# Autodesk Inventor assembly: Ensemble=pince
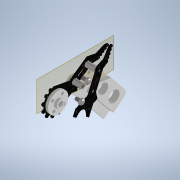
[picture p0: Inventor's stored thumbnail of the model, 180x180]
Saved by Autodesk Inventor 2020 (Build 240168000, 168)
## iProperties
Created: 2021-10
Part Number: Ensemble=pince
Document SubType Name: Assembly
Designer: bruno
Author: bruno
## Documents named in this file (6)
- C:\Users\bruno\OneDrive\Bureau\Robot-Inventor\Robot-equillibrage\Ensemble-pince.iam
- C:\Users\bruno\OneDrive\Bureau\Robot-Inventor\Robot-equillibrage\Ensemble-doigt.iam
- C:\Users\bruno\OneDrive\Bureau\Robot-Inventor\Robot-equillibrage\pince-2.ipt
- C:\Users\bruno\OneDrive\Bureau\Robot-Inventor\Robot-equillibrage\embout-servo.ipt
- C:\Users\bruno\Documents\Inventor\Content Center Files\R2020\fr-FR\ANSI B18.6.7M(01)\ANSI B18.6.7M - M3x0,5 x 5(5).ipt
- C:\Users\bruno\OneDrive\Bureau\Robot-Inventor\Robot-equillibrage\pince-uhl-G.ipt
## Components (7 placed, 5 different names)
1. Ensemble-doigt:1 [sub-assembly] — Placage:1, Placage:2, Placage:8, Logement:2, Logement:3
2. pince-2:1 — Logement:3, Logement:4, Logement:5
3. embout-servo:1 — Placage:1, Placage:2, Placage:7
4. Vis à tête tronconique à empreinte cruciforme - Type IA - Métrique M3x0,5 x 5:1 — Logement:4
5. Vis à tête tronconique à empreinte cruciforme - Type IA - Métrique M3x0,5 x 5:2 — Logement:5
6. Vis à tête tronconique à empreinte cruciforme - Type IA - Métrique M3x0,5 x 5:3 — Placage:7, Placage:8
7. pince-uhl-G:1 — Logement:2
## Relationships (8: Mate 4, Insert 4)
- Placage:1 [Mate]: Ensemble-doigt:1 ↔ embout-servo:1
- Placage:2 [Mate]: Ensemble-doigt:1 ↔ embout-servo:1
- Placage:7 [Mate]: embout-servo:1 ↔ Vis à tête tronconique à empreinte cruciforme - Type IA - Métrique M3x0,5 x 5:3
- Placage:8 [Mate]: Ensemble-doigt:1 ↔ Vis à tête tronconique à empreinte cruciforme - Type IA - Métrique M3x0,5 x 5:3
- Logement:2 [Insert]: Ensemble-doigt:1 ↔ pince-uhl-G:1
- Logement:3 [Insert]: Ensemble-doigt:1 ↔ pince-2:1
- Logement:4 [Insert]: pince-2:1 ↔ Vis à tête tronconique à empreinte cruciforme - Type IA - Métrique M3x0,5 x 5:1
- Logement:5 [Insert]: pince-2:1 ↔ Vis à tête tronconique à empreinte cruciforme - Type IA - Métrique M3x0,5 x 5:2
